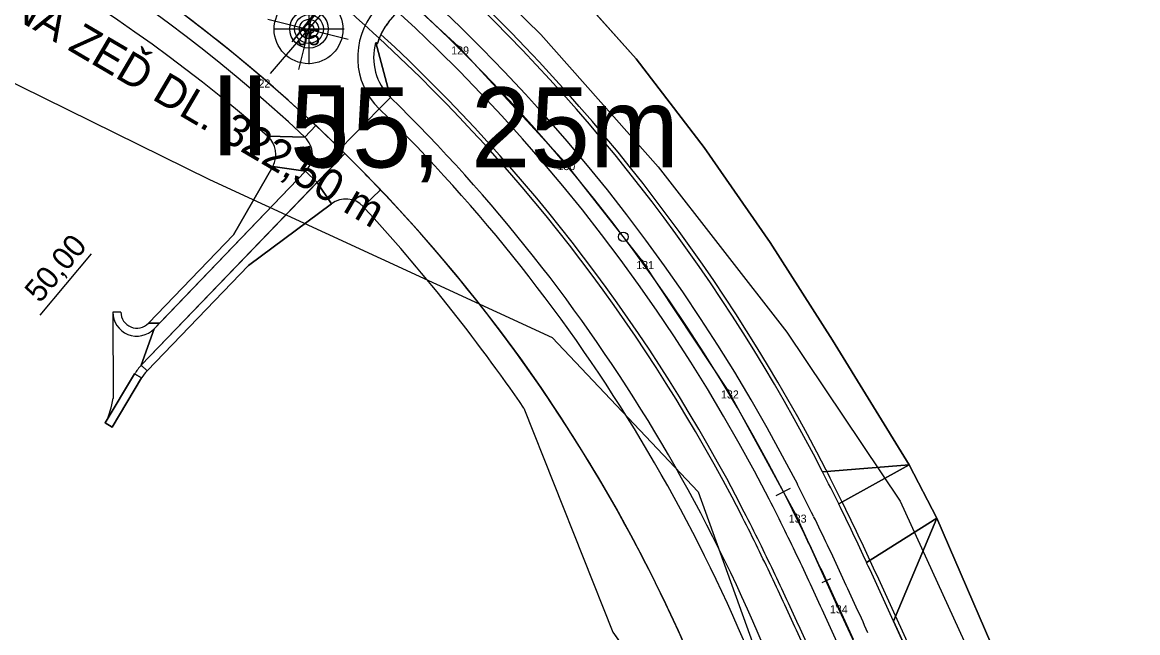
# Model space of a CAD drawing. Extents: x -606444 to -604546, y -1158114 to -1156869.
# Drawn here: x -605244.8 to -605105.4, y -1157260.9 to -1157184.6 of the extents above; entities that cross this region are included whole.
import ezdxf

# ---------------------------------------------------------------- set-up
doc = ezdxf.new("R2010")
doc.units = 0
for name, color, linetype in [('0_sondy', 7, 'Continuous'), ('B_CHOD', 7, 'Continuous'), ('B_TRAM', 7, 'Continuous'), ('B_VOZ', 7, 'Continuous'), ('B_ZELEN', 7, 'Continuous'), ('geofyzikální profily_předběžný GTP', 7, 'Continuous'), ('jádrové vrty_předběžný GTP', 7, 'Continuous'), ('netisk', 7, 'Continuous'), ('netisk2', 7, 'Continuous'), ('NS_VB', 7, 'Continuous'), ('NS_VB_OBJ', 7, 'Continuous'), ('NS_VB_POP', 7, 'Continuous'), ('OSA', 7, 'Continuous'), ('OSAPOP', 7, 'Continuous'), ('podélný profil trasou tramvaje', 7, 'Continuous'), ('sondy současného průzkumu', 7, 'Continuous'), ('stabilitní profily_předběžný GTP', 7, 'Continuous')]:
    doc.layers.add(name, color=color, linetype=linetype)

# ---------------------------------------------------------------- blocks, each defined once
blk = doc.blocks.new('709')
for p, q in [((0, 2.2), (0, -2.2)), ((-2.2, 0), (2.2, 0))]:
    blk.add_line(p, q)
for radius in [1.2, 0.9, 0.6, 0.3]:
    blk.add_circle((0, 0), radius)
blk = doc.blocks.new('IG vrt podr')
at = {"layer": 'sondy současného průzkumu'}
for p, q in [((0.412, 1.649), (-0.418, -1.672)), ((-1.698, 0.422), (1.644, -0.408))]:
    blk.add_line(p, q, dxfattribs=at)
blk.add_circle((-0.002, 0.001), 1.434, dxfattribs=at)

msp = doc.modelspace()

# ---------------------------------------------------------------- linework, layer by layer
for p, q in [((-605209, -1157185.48), (-605209.1, -1157185.38)), ((-605209, -1157185.48), (-605209.1, -1157185.58)), ((-605209, -1157185.48), (-605208.9, -1157185.38)), ((-605209, -1157185.48), (-605208.9, -1157185.58)), ((-605190.28, -1157187.63), (-605190.38, -1157187.53)), ((-605190.28, -1157187.63), (-605190.38, -1157187.73)), ((-605190.28, -1157187.63), (-605190.18, -1157187.53)), ((-605190.28, -1157187.63), (-605190.18, -1157187.73)), ((-605215.11, -1157191.76), (-605215.21, -1157191.66)), ((-605215.11, -1157191.76), (-605215.21, -1157191.86)), ((-605215.11, -1157191.76), (-605215.01, -1157191.66)), ((-605215.11, -1157191.76), (-605215.01, -1157191.86)), ((-605176.96, -1157202.08), (-605177.06, -1157201.98)), ((-605176.96, -1157202.08), (-605177.06, -1157202.18)), ((-605176.96, -1157202.08), (-605176.86, -1157201.98)), ((-605176.96, -1157202.08), (-605176.86, -1157202.18)), ((-605167.27, -1157214.45), (-605167.37, -1157214.35)), ((-605167.27, -1157214.45), (-605167.37, -1157214.55)), ((-605167.27, -1157214.45), (-605167.17, -1157214.35)), ((-605167.27, -1157214.45), (-605167.17, -1157214.55)), ((-605156.56, -1157230.62), (-605156.66, -1157230.52)), ((-605156.56, -1157230.62), (-605156.66, -1157230.72)), ((-605156.56, -1157230.62), (-605156.46, -1157230.52)), ((-605156.56, -1157230.62), (-605156.46, -1157230.72)), ((-605148.09, -1157246.14), (-605148.19, -1157246.04)), ((-605148.09, -1157246.14), (-605148.19, -1157246.24)), ((-605148.09, -1157246.14), (-605147.99, -1157246.04)), ((-605148.09, -1157246.14), (-605147.99, -1157246.24)), ((-605142.94, -1157257.48), (-605143.04, -1157257.38)), ((-605142.94, -1157257.48), (-605143.04, -1157257.58)), ((-605142.94, -1157257.48), (-605142.84, -1157257.38)), ((-605142.94, -1157257.48), (-605142.84, -1157257.58))]:
    msp.add_line(p, q)
at = {"layer": 'B_CHOD'}
for points in [[(-605199, -1157184.61), (-605192.99, -1157177.59), (-605192.23, -1157176.7)], [(-605200.61, -1157187.13), (-605200.41, -1157187.33)], [(-605198.76, -1157194), (-605200.16, -1157195.43)], [(-605200.16, -1157195.43), (-605198.76, -1157194)], [(-605209.48, -1157198.96), (-605208.11, -1157197.51)], [(-605208.11, -1157197.51), (-605209.48, -1157198.96)], [(-605209.37, -1157203.23), (-605207.93, -1157204.62), (-605204.46, -1157201.02)], [(-605229.91, -1157227.47), (-605207.93, -1157204.62), (-605209.37, -1157203.23), (-605228.3, -1157222.91), (-605229.91, -1157227.47)], [(-605233.47, -1157220.84), (-605233.44, -1157231.61)], [(-605229.91, -1157227.47), (-605228.3, -1157222.91)], [(-605234.41, -1157234.68), (-605230.74, -1157228.55)]]:
    msp.add_lwpolyline(points, dxfattribs=at)
for centre, radius, start, end in [((-605345.26, -1157343.76), 200.5, 46.8415, 97.5799), ((-605345.26, -1157343.76), 198.5, 46.8415, 97.5799), ((-605193.87, -1157189), 9, 139.4626, 225.6318), ((-605193.87, -1157188.99), 6.75, 139.4591, 152.5756), ((-605193.87, -1157189), 7, 164.5789, 225.6318), ((-605193.87, -1157189), 6.75, 152.5721, 165.6815), ((-605345.26, -1157343.76), 209.5, 16.4017, 45.6318), ((-605345.26, -1157343.76), 207.5, 16.4017, 45.6318), ((-605345.26, -1157343.76), 200.5, 45.3942, 46.8415), ((-605211.53, -1157201.15), 3, 316.1039, 46.8415), ((-605230.47, -1157220.83), 3, 180.1381, 316.1039), ((-605225.59, -1157231.63), 6, 136.1039, 149.1155), ((-605241.9, -1157230.63), 8.51, 331.6356, 353.4137)]:
    msp.add_arc(centre, radius, start, end, dxfattribs=at)
at = {"layer": 'B_TRAM'}
msp.add_line((-605111.14, -1157313.67), (-605135.89, -1157259.45), dxfattribs=at)
for centre, radius, start, end in [((-605345.33, -1157343.85), 225.5, 27.1946, 47.5015), ((-605193.87, -1157188.99), 6.75, 139.4591, 154.7431), ((-605345.33, -1157343.85), 214.5, 27.1951, 47.3372), ((-605369.03, -1157355.92), 252.09, 26.1514, 27.1745), ((-605369.03, -1157355.92), 241.09, 26.1524, 27.174), ((-605483.53, -1157411.8), 379.5, 24.8788, 26.1047), ((-605483.53, -1157411.8), 368.5, 24.8788, 26.104), ((-606162.13, -1157726.49), 1127.51, 24.47047, 24.87882), ((-606162.13, -1157726.49), 1116.51, 24.47014, 24.87882)]:
    msp.add_arc(centre, radius, start, end, dxfattribs=at)
at = {"layer": 'B_VOZ'}
for points in [[(-605200.16, -1157195.43), (-605205.05, -1157200.43)], [(-605205.05, -1157200.43), (-605200.16, -1157195.43)]]:
    msp.add_lwpolyline(points, dxfattribs=at)
for centre, radius, start, end in [((-605345.26, -1157343.76), 200.5, 45.6318, 53.0471), ((-605193.87, -1157189), 9, 139.4626, 225.6318), ((-605345.26, -1157343.76), 207.5, 16.4017, 45.6318), ((-605345.26, -1157343.76), 200.5, 16.4017, 45.6318)]:
    msp.add_arc(centre, radius, start, end, dxfattribs=at)
at = {"layer": 'B_ZELEN'}
for points in [[(-605144.76, -1157240.79), (-605133.95, -1157239.93), (-605143.53, -1157224.32), (-605151.31, -1157212.15), (-605159.56, -1157200.24), (-605168.04, -1157189.17), (-605177.2, -1157178.94), (-605178.68, -1157180.28), (-605182.02, -1157176.56)], [(-605200.41, -1157187.33), (-605200.61, -1157187.13), (-605198.76, -1157194)], [(-605198.76, -1157194), (-605200.61, -1157187.13)], [(-605209.48, -1157198.96), (-605214.11, -1157198.86)], [(-605214.11, -1157198.86), (-605209.48, -1157198.96)], [(-605204.46, -1157201.02), (-605207.93, -1157204.62), (-605206.14, -1157207.28)], [(-605218.38, -1157211.16), (-605229.02, -1157222.22), (-605227.64, -1157222.22), (-605209.37, -1157203.23), (-605213.48, -1157202.62), (-605218.38, -1157211.16)], [(-605213.48, -1157202.62), (-605209.37, -1157203.23)], [(-605216.53, -1157215), (-605206.14, -1157207.28), (-605207.93, -1157204.62), (-605229.91, -1157227.47), (-605229.19, -1157228.16), (-605216.53, -1157215)], [(-605200, -1157205.56), (-605202.18, -1157207.62)], [(-605202.18, -1157207.62), (-605200, -1157205.56)], [(-605232.47, -1157220.84), (-605233.47, -1157220.84)], [(-605228.3, -1157222.91), (-605227.64, -1157222.22), (-605229.02, -1157222.22)], [(-605229.19, -1157228.16), (-605229.91, -1157227.47)], [(-605233.55, -1157235.19), (-605229.88, -1157229.06), (-605230.74, -1157228.55), (-605234.41, -1157234.68), (-605233.55, -1157235.19)], [(-605230.74, -1157228.55), (-605229.88, -1157229.06)], [(-605182.08, -1157232.83), (-605170.99, -1157260.85), (-605165.74, -1157268.19)], [(-605142.74, -1157244.81), (-605133.95, -1157239.93), (-605144.76, -1157240.79)], [(-605139.25, -1157252.14), (-605130.49, -1157246.6), (-605133.95, -1157239.93), (-605142.74, -1157244.81)], [(-605135.89, -1157259.45), (-605130.49, -1157246.6), (-605139.25, -1157252.14)], [(-605121.47, -1157267.41), (-605130.49, -1157246.6), (-605135.89, -1157259.45), (-605111.14, -1157313.67)]]:
    msp.add_lwpolyline(points, dxfattribs=at)
for centre, radius, start, end in [((-605345.26, -1157343.76), 198.5, 46.8415, 97.5799), ((-605345.97, -1157349.67), 200.33, 48.8336, 96.6948), ((-605345.33, -1157343.85), 225.5, 27.1946, 47.5015), ((-605193.87, -1157189), 7, 164.5789, 225.6318), ((-605193.87, -1157189), 6.75, 154.7384, 165.6815), ((-605345.33, -1157343.85), 214.5, 27.1951, 47.3372), ((-605345.26, -1157343.76), 209.5, 16.4017, 45.6318), ((-605216.08, -1157201.12), 3, 330.1393, 48.8336), ((-605211.53, -1157201.15), 3, 316.1039, 46.8415), ((-605345.26, -1157343.76), 200.5, 43.5758, 45.3942), ((-605204.35, -1157209.69), 3, 43.5758, 126.5961), ((-605345.26, -1157343.76), 200.5, 16.4017, 43.5758), ((-605371.15, -1157362.97), 229.53, 34.541, 42.594), ((-605230.47, -1157220.83), 3, 180.1376, 316.1039), ((-605230.47, -1157220.83), 2, 180.1376, 316.1039), ((-605225.59, -1157231.63), 6, 136.1039, 149.1155), ((-605225.59, -1157231.63), 5, 136.1039, 149.1155), ((-605369.03, -1157355.92), 252.09, 26.1514, 27.1745), ((-605369.03, -1157355.92), 241.09, 26.1524, 27.174), ((-605483.53, -1157411.8), 379.5, 24.8788, 26.1047), ((-605483.53, -1157411.8), 368.5, 24.8789, 26.104), ((-606162.13, -1157726.49), 1127.51, 24.47047, 24.87882), ((-606162.13, -1157726.49), 1116.51, 24.47014, 24.87885)]:
    msp.add_arc(centre, radius, start, end, dxfattribs=at)
at = {"layer": 'geofyzikální profily_předběžný GTP'}
for points in [[(-605670.78, -1157141.05), (-605656.02, -1157139.47), (-605613.88, -1157139.36), (-605584.8, -1157137.32), (-605531.41, -1157136.33), (-605491.56, -1157133.4), (-605482.07, -1157135.61), (-605438.78, -1157126.66), (-605383.23, -1157124.52), (-605352.34, -1157123.33), (-605321.95, -1157126), (-605284.14, -1157130.42), (-605243.3, -1157142.6), (-605207.83, -1157158.83), (-605179.98, -1157186.15), (-605165.29, -1157202.67), (-605149.23, -1157223.34), (-605135.07, -1157244.47), (-605115.92, -1157286.28), (-605103.22, -1157315.84), (-605095.33, -1157330.32), (-605036.97, -1157403.36), (-604999.08, -1157442.54), (-604970.8, -1157468.35)], [(-605668.89, -1157175.56), (-605638.05, -1157172.71), (-605616.09, -1157172.84), (-605512.92, -1157173.16), (-605468.49, -1157175.65), (-605413.5, -1157174.06), (-605313.44, -1157169.44), (-605274.57, -1157178.01), (-605221.39, -1157204.27), (-605178.57, -1157224), (-605160.32, -1157243.28), (-605143.64, -1157289.5), (-605117.17, -1157349.93), (-605096.21, -1157389.16), (-605065.9, -1157426.81), (-605053.52, -1157443.58), (-605045.82, -1157465.15), (-605020.21, -1157502.2)]]:
    msp.add_lwpolyline(points, dxfattribs=at)
at = {"layer": 'netisk'}
msp.add_line((-605202.52, -1157176.17), (-605211.11, -1157187.04), dxfattribs=at)
at = {"layer": 'netisk2'}
msp.add_line((-605211.04, -1157187.04), (-605202.23, -1157176.75), dxfattribs=at)
at = {"layer": 'NS_VB'}
for p, q in [((-605178.11, -1157177.92), (-605168.04, -1157189.17)), ((-605200.61, -1157187.13), (-605200.41, -1157187.33)), ((-605168.04, -1157189.17), (-605159.56, -1157200.24)), ((-605204.46, -1157201.02), (-605229.91, -1157227.47)), ((-605159.56, -1157200.24), (-605151.31, -1157212.15)), ((-605209.37, -1157203.23), (-605228.3, -1157222.91)), ((-605218.38, -1157211.16), (-605213.48, -1157202.62)), ((-605206.14, -1157207.28), (-605216.53, -1157215)), ((-605218.38, -1157211.16), (-605229.02, -1157222.22)), ((-605151.31, -1157212.15), (-605143.53, -1157224.32)), ((-605216.53, -1157215), (-605229.19, -1157228.16)), ((-605233.47, -1157220.84), (-605233.44, -1157231.61)), ((-605232.47, -1157220.84), (-605233.47, -1157220.84)), ((-605143.53, -1157224.32), (-605133.95, -1157239.93)), ((-605230.74, -1157228.55), (-605234.41, -1157234.68)), ((-605229.88, -1157229.06), (-605233.55, -1157235.19)), ((-605182.08, -1157232.83), (-605170.99, -1157260.85)), ((-605233.55, -1157235.19), (-605234.41, -1157234.68)), ((-605133.95, -1157239.93), (-605130.49, -1157246.6)), ((-605130.49, -1157246.6), (-605121.47, -1157267.41)), ((-605170.99, -1157260.85), (-605165.74, -1157268.19))]:
    msp.add_line(p, q, dxfattribs=at)
msp.add_lwpolyline([(-605111.14, -1157313.67), (-605135.89, -1157259.45)], dxfattribs=at)
for centre, radius, start, end in [((-605345.26, -1157343.76), 200.5, 16.4017, 97.5799), ((-605345.26, -1157343.76), 198.5, 46.8415, 97.5799), ((-605345.97, -1157349.67), 200.33, 48.8336, 96.6948), ((-605345.33, -1157343.85), 225.5, 27.1946, 47.5015), ((-605193.87, -1157189), 9, 139.4626, 225.6318), ((-605193.87, -1157189), 6.75, 139.4626, 165.6816), ((-605193.87, -1157189), 7, 164.5789, 225.6318), ((-605345.33, -1157343.85), 214.5, 27.1951, 47.3372), ((-605345.26, -1157343.76), 209.5, 16.4017, 45.6318), ((-605345.26, -1157343.76), 207.5, 16.4017, 45.6318), ((-605216.08, -1157201.12), 3, 330.1393, 48.8336), ((-605211.53, -1157201.15), 3, 316.1039, 46.8415), ((-605204.35, -1157209.69), 3, 43.5758, 126.5961), ((-605371.15, -1157362.97), 229.53, 34.541, 42.594), ((-605230.47, -1157220.83), 3, 180.1376, 316.1039), ((-605230.47, -1157220.83), 2, 180.1376, 316.1039), ((-605225.59, -1157231.63), 6, 136.1039, 149.1155), ((-605225.59, -1157231.63), 5, 136.1039, 149.1155), ((-605241.9, -1157230.63), 8.51, 331.6356, 353.4137), ((-605369.03, -1157355.92), 252.09, 26.1514, 27.1745), ((-605369.03, -1157355.92), 241.09, 26.1524, 27.174), ((-605483.53, -1157411.8), 379.5, 24.8788, 26.1047), ((-605483.53, -1157411.8), 368.5, 24.8788, 26.104), ((-606162.13, -1157726.49), 1127.51, 24.47047, 24.87882), ((-606162.13, -1157726.49), 1116.51, 24.47014, 24.87882)]:
    msp.add_arc(centre, radius, start, end, dxfattribs=at)
at = {"layer": 'NS_VB_OBJ'}
msp.add_lwpolyline([(-605110.83, -1157313.14), (-605135.44, -1157259.24)], dxfattribs=at)
for centre, radius, start, end in [((-605345.33, -1157343.85), 214, 47.2894, 51.3884), ((-605345.33, -1157343.85), 226, 27.1946, 47.5059), ((-605345.33, -1157343.85), 214, 27.1951, 47.2893), ((-605369.03, -1157355.92), 252.59, 26.1513, 27.1745), ((-605483.53, -1157411.8), 380, 24.8788, 26.1048), ((-605369.03, -1157355.92), 240.59, 26.1525, 27.174), ((-605483.53, -1157411.8), 368, 24.8788, 26.104), ((-606162.13, -1157726.49), 1128.01, 24.47048, 24.87882), ((-606162.13, -1157726.49), 1116.01, 24.47012, 24.87882)]:
    msp.add_arc(centre, radius, start, end, dxfattribs=at)
at = {"layer": 'OSA'}
for centre, radius, start, end in [((-605345.33, -1157343.85), 222, 27.1947, 92.2052), ((-605345.33, -1157343.85), 220, 27.1948, 92.2049), ((-605345.33, -1157343.85), 218, 27.1949, 92.2045), ((-605369.03, -1157355.92), 248.59, 26.1517, 27.1743), ((-605369.03, -1157355.92), 244.59, 26.1521, 27.1741), ((-605369.03, -1157355.92), 246.59, 26.1519, 27.1742), ((-605483.53, -1157411.8), 376, 24.8788, 26.1045), ((-605483.53, -1157411.8), 372, 24.8788, 26.1043), ((-605483.53, -1157411.8), 374, 24.8788, 26.1044), ((-606162.13, -1157726.49), 1124.01, 24.47036, 24.87882), ((-606162.13, -1157726.49), 1120.01, 24.47024, 24.87882), ((-606162.13, -1157726.49), 1122.01, 24.4703, 24.87882)]:
    msp.add_arc(centre, radius, start, end, dxfattribs=at)
at = {"layer": 'OSAPOP'}
for p, q in [((-605242.56, -1157221.22), (-605236.13, -1157213.56)), ((-605150.54, -1157243.76), (-605148.76, -1157242.85)), ((-605144.82, -1157254.63), (-605143.73, -1157254.12))]:
    msp.add_line(p, q, dxfattribs=at)
msp.add_circle((-605169.66, -1157211.42), 0.6, dxfattribs=at)
at = {"layer": 'podélný profil trasou tramvaje'}
msp.add_lwpolyline([(-605085.67, -1157373.96), (-605102.48, -1157348.99), (-605137.42, -1157269.35), (-605142.94, -1157257.48), (-605148.09, -1157246.14), (-605156.56, -1157230.62), (-605167.27, -1157214.45), (-605176.96, -1157202.08), (-605190.28, -1157187.63), (-605201.93, -1157176.87), (-605210.19, -1157170.25), (-605214.51, -1157166.83), (-605234.53, -1157153.68), (-605243.13, -1157148.91), (-605255.42, -1157142.97), (-605270.4, -1157136.88), (-605273.54, -1157135.89), (-605289.22, -1157131.03), (-605304.97, -1157127.5), (-605318.55, -1157125.25), (-605341.87, -1157123.88), (-605358.23, -1157124.22), (-605590.31, -1157143.82)], dxfattribs=at)
at = {"layer": 'stabilitní profily_předběžný GTP'}
msp.add_lwpolyline([(-605213.75, -1157191.02), (-605182.46, -1157154.53)], dxfattribs=at)

# ---------------------------------------------------------------- block references
at = {"layer": '0_sondy', "xscale": 2, "yscale": 2}
msp.add_blockref('709', (-605208.95, -1157185.44), dxfattribs=at)
at = {"layer": 'jádrové vrty_předběžný GTP', "xscale": 3, "yscale": 3}
msp.add_blockref('IG vrt podr', (-605209, -1157185.48), dxfattribs=at)

# ---------------------------------------------------------------- texts
for s, height, p in [('J5', 2, (-605210.39, -1157187.48)), ('129', 1, (-605191.18, -1157188.63)), ('122', 1, (-605216.01, -1157192.76)), ('130', 1, (-605177.9, -1157203.08)), ('131', 1, (-605168.05, -1157215.45)), ('132', 1, (-605157.46, -1157231.62)), ('133', 1, (-605148.99, -1157247.14)), ('134', 1, (-605143.84, -1157258.48))]:
    msp.add_text(s, height=height).set_placement(p)
at = {"layer": '0_sondy'}
msp.add_text('5', height=10, dxfattribs=at).set_placement((-605211.33, -1157202.5))
at = {"layer": 'jádrové vrty_předběžný GTP'}
msp.add_text('J5, 25m', height=10, dxfattribs=at).set_placement((-605210.26, -1157202.75))
at = {"layer": 'NS_VB_POP'}
msp.add_text('OPĚRNÁ ZEĎ DL. 322,50 m', height=4, rotation=329.5835, dxfattribs=at).set_placement((-605259.99, -1157175.79))
at = {"layer": 'OSAPOP'}
msp.add_text('50,00', height=2.8, rotation=50.0321, dxfattribs=at).set_placement((-605242.58, -1157219.8))
at = {"layer": 'stabilitní profily_předběžný GTP'}
msp.add_text('II', height=10, dxfattribs=at).set_placement((-605221.28, -1157201.22))

doc.saveas('drawing.dxf')
